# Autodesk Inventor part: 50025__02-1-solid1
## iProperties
Created: 2010-10
Part Number: 50025__02-1-solid1
Document SubType Name: Modeling
Designer: Administrator
Density: 7.85 g/cm^3
Material: Steel
Mass: 2.10869 g
Surface Area: 3.47724 cm^2
Volume: 0.268623 cm^3
Author: Administrator
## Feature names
1. Base1
